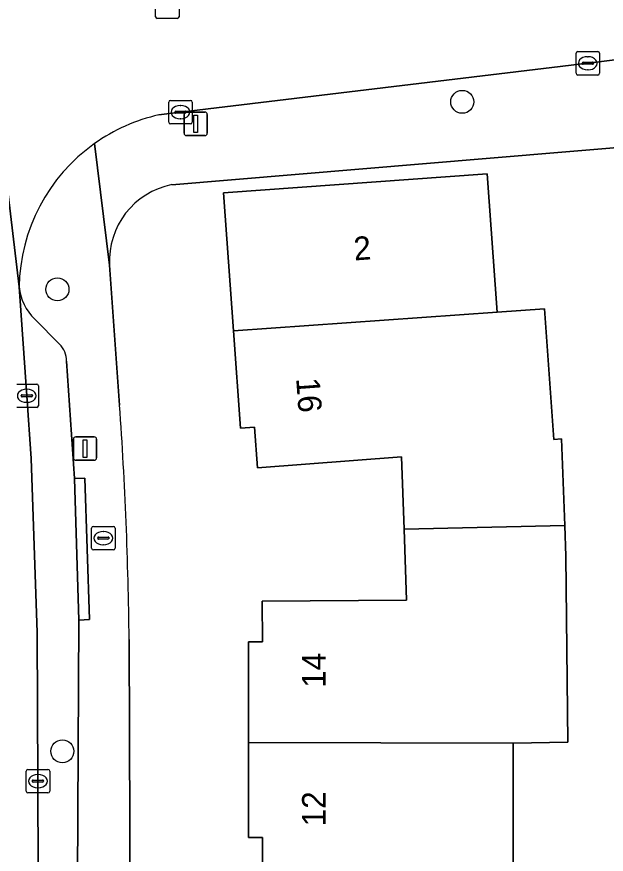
# Model space of a CAD drawing. Extents: x 162879 to 165540, y 384011 to 385181.
# Drawn here: x 163797.54 to 163822.64, y 384339.68 to 384375.35 of the extents above; entities that cross this region are included whole.
import ezdxf

# ---------------------------------------------------------------- set-up
doc = ezdxf.new("R2010")
doc.units = 0
for name, color, linetype in [('IMGEO_Boom', 7, 'Continuous'), ('IMGEO_Brandkraan', 7, 'Continuous'), ('IMGEO_Erf', 7, 'Continuous'), ('IMGEO_Kolk', 7, 'Continuous'), ('IMGEO_Lichtmast', 7, 'Continuous'), ('IMGEO_Muur', 7, 'Continuous'), ('IMGEO_Pand', 7, 'Continuous'), ('IMGEO_Pand_nummerreeks', 7, 'Continuous'), ('IMGEO_Parkeervlak_open', 7, 'Continuous'), ('IMGEO_Rijbaan_lokaal_open', 7, 'Continuous'), ('IMGEO_Voetpad_open', 7, 'Continuous')]:
    doc.layers.add(name, color=color, linetype=linetype)

msp = doc.modelspace()

# ---------------------------------------------------------------- linework, layer by layer
at = {"layer": 'IMGEO_Boom'}
for centre in [(163816.507, 384371.726), (163799.272, 384363.738), (163799.484, 384344.065)]:
    msp.add_circle(centre, 0.489, dxfattribs=at)
at = {"layer": 'IMGEO_Brandkraan'}
for p, q in [((163800.727, 384352.718), (163800.727, 384353.57)), ((163800.802, 384353.644), (163801.654, 384353.644)), ((163801.728, 384353.57), (163801.728, 384352.718)), ((163801.215, 384353.424), (163801.24, 384353.424)), ((163800.986, 384353.138), (163800.986, 384353.15)), ((163801.424, 384353.101), (163801.026, 384353.101)), ((163801.029, 384353.187), (163801.427, 384353.187)), ((163801.238, 384352.864), (163801.213, 384352.864)), ((163801.47, 384353.15), (163801.47, 384353.138)), ((163801.654, 384352.644), (163800.802, 384352.644))]:
    msp.add_line(p, q, dxfattribs=at)
for points in [[(163800.727, 384352.718), (163800.727, 384353.57)], [(163800.802, 384353.644), (163801.654, 384353.644)], [(163801.728, 384353.57), (163801.728, 384352.718)], [(163801.654, 384352.644), (163800.802, 384352.644)]]:
    msp.add_lwpolyline(points, dxfattribs=at)
for centre, radius, start, end in [((163800.804, 384353.568), 0.0765, 91.552, 178.448), ((163800.804, 384353.568), 0.0765, 91.552, 178.448), ((163801.652, 384353.568), 0.0765, 1.552, 88.448), ((163801.652, 384353.568), 0.0765, 1.552, 88.448), ((163801.026, 384353.147), 0.0403, 85.8775, 175.7526), ((163801.023, 384353.137), 0.0366, 178.938, 274.7102), ((163801.427, 384353.144), 0.043, 264.8664, 352.4533), ((163801.431, 384353.149), 0.0386, 1.7309, 96.639), ((163800.804, 384352.72), 0.0765, 181.552, 268.448), ((163800.804, 384352.72), 0.0765, 181.552, 268.448), ((163801.652, 384352.72), 0.0765, 271.552, 358.448), ((163801.652, 384352.72), 0.0765, 271.552, 358.448)]:
    msp.add_arc(centre, radius, start, end, dxfattribs=at)
for centre, major_axis, ratio, start_param, end_param in [((163801.214, 384353.144), (-0.387, 0.002), 0.722429, 4.712389, 7.853982), ((163801.239, 384353.144), (-0.39, 0.002), 0.717154, 1.570796, 4.712389)]:
    msp.add_ellipse(centre, major_axis=major_axis, ratio=ratio, start_param=start_param, end_param=end_param, dxfattribs=at)
at = {"layer": 'IMGEO_Erf'}
for points in [[(163871.845, 384381.733), (163828.311, 384370.22), (163828.207, 384370.211), (163817.519, 384369.317), (163804.137, 384368.197)], [(163808.008, 384338.663), (163808.008, 384340.393), (163807.408, 384340.393), (163807.408, 384344.433), (163807.408, 384348.733), (163808.008, 384348.733), (163807.996, 384350.455), (163814.136, 384350.498), (163814.032, 384353.524), (163813.926, 384356.611), (163807.795, 384356.132), (163807.659, 384357.872), (163807.061, 384357.829), (163806.762, 384361.971), (163806.338, 384367.853), (163817.574, 384368.663), (163817.999, 384362.768), (163820.004, 384362.913), (163820.406, 384357.348), (163820.735, 384357.372), (163820.87, 384353.677), (163820.918, 384352.376), (163821.006, 384344.449), (163818.676, 384344.414), (163818.677, 384339.004)], [(163801.492, 384364.772), (163801.92, 384358.803)], [(163802.324, 384348.829), (163802.427, 384320.83)]]:
    msp.add_lwpolyline(points, dxfattribs=at)
for centre, radius, start, end in [((163804.796, 384364.955), 3.309, 101.4804, 183.1645), ((163636.355, 384347.102), 165.978, 0.59633, 4.0427)]:
    msp.add_arc(centre, radius, start, end, dxfattribs=at)
at = {"layer": 'IMGEO_Kolk'}
for p, q in [((163803.448, 384375.349), (163803.448, 384376.201)), ((163804.449, 384376.201), (163804.449, 384375.349)), ((163804.375, 384375.275), (163803.523, 384375.275)), ((163821.351, 384372.94), (163821.351, 384373.792)), ((163821.426, 384373.866), (163822.278, 384373.866)), ((163821.839, 384373.646), (163821.864, 384373.646)), ((163822.352, 384373.792), (163822.352, 384372.94)), ((163821.61, 384373.36), (163821.61, 384373.372)), ((163822.048, 384373.323), (163821.65, 384373.323)), ((163821.653, 384373.409), (163822.051, 384373.409)), ((163822.094, 384373.372), (163822.094, 384373.36)), ((163822.278, 384372.866), (163821.426, 384372.866)), ((163821.862, 384373.086), (163821.837, 384373.086)), ((163804.085, 384371.784), (163804.937, 384371.784)), ((163804.01, 384370.858), (163804.01, 384371.71)), ((163804.498, 384371.564), (163804.523, 384371.564)), ((163805.011, 384371.71), (163805.011, 384370.858)), ((163804.269, 384371.278), (163804.269, 384371.29)), ((163804.707, 384371.241), (163804.309, 384371.241)), ((163804.312, 384371.327), (163804.71, 384371.327)), ((163804.753, 384371.29), (163804.753, 384371.278)), ((163804.937, 384370.784), (163804.085, 384370.784)), ((163804.521, 384371.004), (163804.496, 384371.004)), ((163797.541, 384359.707), (163798.393, 384359.707)), ((163798.467, 384359.633), (163798.467, 384358.781)), ((163797.954, 384359.487), (163797.979, 384359.487)), ((163797.725, 384359.201), (163797.725, 384359.213)), ((163798.163, 384359.164), (163797.765, 384359.164)), ((163797.768, 384359.25), (163798.166, 384359.25)), ((163797.977, 384358.927), (163797.952, 384358.927)), ((163798.209, 384359.213), (163798.209, 384359.201)), ((163798.393, 384358.707), (163797.541, 384358.707)), ((163797.942, 384342.369), (163797.942, 384343.221)), ((163798.017, 384343.295), (163798.869, 384343.295)), ((163798.943, 384343.221), (163798.943, 384342.369)), ((163798.43, 384343.075), (163798.455, 384343.075)), ((163798.201, 384342.789), (163798.201, 384342.801)), ((163798.639, 384342.752), (163798.241, 384342.752)), ((163798.244, 384342.838), (163798.642, 384342.838)), ((163798.453, 384342.515), (163798.428, 384342.515)), ((163798.685, 384342.801), (163798.685, 384342.789)), ((163798.869, 384342.295), (163798.017, 384342.295))]:
    msp.add_line(p, q, dxfattribs=at)
for points in [[(163803.448, 384375.349), (163803.448, 384376.201)], [(163804.449, 384376.201), (163804.449, 384375.349)], [(163804.375, 384375.275), (163803.523, 384375.275)], [(163821.351, 384372.94), (163821.351, 384373.792)], [(163821.426, 384373.866), (163822.278, 384373.866)], [(163822.352, 384373.792), (163822.352, 384372.94)], [(163822.278, 384372.866), (163821.426, 384372.866)], [(163804.085, 384371.784), (163804.937, 384371.784)], [(163804.01, 384370.858), (163804.01, 384371.71)], [(163805.011, 384371.71), (163805.011, 384370.858)], [(163804.937, 384370.784), (163804.085, 384370.784)], [(163797.541, 384359.707), (163798.393, 384359.707)], [(163798.467, 384359.633), (163798.467, 384358.781)], [(163798.393, 384358.707), (163797.541, 384358.707)], [(163797.942, 384342.369), (163797.942, 384343.221)], [(163798.017, 384343.295), (163798.869, 384343.295)], [(163798.943, 384343.221), (163798.943, 384342.369)], [(163798.869, 384342.295), (163798.017, 384342.295)]]:
    msp.add_lwpolyline(points, dxfattribs=at)
for centre, radius, start, end in [((163803.525, 384375.351), 0.0765, 181.552, 268.448), ((163803.525, 384375.351), 0.0765, 181.552, 268.448), ((163804.373, 384375.351), 0.0765, 271.552, 358.448), ((163804.373, 384375.351), 0.0765, 271.552, 358.448), ((163821.428, 384373.79), 0.0765, 91.552, 178.448), ((163821.428, 384373.79), 0.0765, 91.552, 178.448), ((163822.276, 384373.79), 0.0765, 1.552, 88.448), ((163822.276, 384373.79), 0.0765, 1.552, 88.448), ((163821.65, 384373.369), 0.0403, 85.8775, 175.7526), ((163821.647, 384373.359), 0.0366, 178.938, 274.7102), ((163822.051, 384373.366), 0.043, 264.8664, 352.4533), ((163822.055, 384373.371), 0.0386, 1.7309, 96.639), ((163821.428, 384372.942), 0.0765, 181.552, 268.448), ((163821.428, 384372.942), 0.0765, 181.552, 268.448), ((163822.276, 384372.942), 0.0765, 271.552, 358.448), ((163822.276, 384372.942), 0.0765, 271.552, 358.448), ((163804.087, 384371.708), 0.0765, 91.552, 178.448), ((163804.087, 384371.708), 0.0765, 91.552, 178.448), ((163804.935, 384371.708), 0.0765, 1.552, 88.448), ((163804.935, 384371.708), 0.0765, 1.552, 88.448), ((163804.309, 384371.287), 0.0403, 85.8775, 175.7526), ((163804.306, 384371.277), 0.0366, 178.938, 274.7102), ((163804.71, 384371.284), 0.043, 264.8664, 352.4533), ((163804.714, 384371.289), 0.0386, 1.7309, 96.639), ((163804.087, 384370.86), 0.0765, 181.552, 268.448), ((163804.087, 384370.86), 0.0765, 181.552, 268.448), ((163804.935, 384370.86), 0.0765, 271.552, 358.448), ((163804.935, 384370.86), 0.0765, 271.552, 358.448), ((163798.391, 384359.631), 0.0765, 1.552, 88.448), ((163798.391, 384359.631), 0.0765, 1.552, 88.448), ((163797.765, 384359.21), 0.0403, 85.8775, 175.7526), ((163797.762, 384359.2), 0.0366, 178.938, 274.7102), ((163798.166, 384359.207), 0.043, 264.8664, 352.4533), ((163798.17, 384359.212), 0.0386, 1.7309, 96.639), ((163798.391, 384358.783), 0.0765, 271.552, 358.448), ((163798.391, 384358.783), 0.0765, 271.552, 358.448), ((163798.019, 384343.219), 0.0765, 91.552, 178.448), ((163798.019, 384343.219), 0.0765, 91.552, 178.448), ((163798.867, 384343.219), 0.0765, 1.552, 88.448), ((163798.867, 384343.219), 0.0765, 1.552, 88.448), ((163798.241, 384342.798), 0.0403, 85.8775, 175.7526), ((163798.238, 384342.788), 0.0366, 178.938, 274.7102), ((163798.642, 384342.795), 0.043, 264.8664, 352.4533), ((163798.646, 384342.8), 0.0386, 1.7309, 96.639), ((163798.019, 384342.371), 0.0765, 181.552, 268.448), ((163798.019, 384342.371), 0.0765, 181.552, 268.448), ((163798.867, 384342.371), 0.0765, 271.552, 358.448), ((163798.867, 384342.371), 0.0765, 271.552, 358.448)]:
    msp.add_arc(centre, radius, start, end, dxfattribs=at)
for centre, major_axis, ratio, start_param, end_param in [((163821.838, 384373.366), (-0.387, 0.002), 0.722429, 4.712389, 7.853982), ((163821.863, 384373.366), (-0.39, 0.002), 0.717154, 1.570796, 4.712389), ((163804.497, 384371.284), (-0.387, 0.002), 0.722429, 4.712389, 7.853982), ((163804.522, 384371.284), (-0.39, 0.002), 0.717154, 1.570796, 4.712389), ((163797.953, 384359.207), (-0.387, 0.002), 0.722429, 4.712389, 7.853982), ((163797.978, 384359.207), (-0.39, 0.002), 0.717154, 1.570796, 4.712389), ((163798.429, 384342.795), (-0.387, 0.002), 0.722429, 4.712389, 7.853982), ((163798.454, 384342.795), (-0.39, 0.002), 0.717154, 1.570796, 4.712389)]:
    msp.add_ellipse(centre, major_axis=major_axis, ratio=ratio, start_param=start_param, end_param=end_param, dxfattribs=at)
at = {"layer": 'IMGEO_Lichtmast'}
for p, q in [((163804.664, 384370.388), (163804.664, 384371.188)), ((163804.664, 384371.188), (163804.664, 384370.388)), ((163804.764, 384371.288), (163805.554, 384371.288)), ((163805.554, 384371.288), (163804.764, 384371.288)), ((163805.654, 384371.188), (163805.654, 384370.388)), ((163805.654, 384370.388), (163805.654, 384371.188)), ((163805.554, 384370.288), (163804.764, 384370.288)), ((163804.764, 384370.288), (163805.554, 384370.288)), ((163799.952, 384356.558), (163799.952, 384357.358)), ((163799.952, 384357.358), (163799.952, 384356.558)), ((163800.052, 384357.458), (163800.842, 384357.458)), ((163800.842, 384357.458), (163800.052, 384357.458)), ((163800.942, 384357.358), (163800.942, 384356.558)), ((163800.942, 384356.558), (163800.942, 384357.358)), ((163800.842, 384356.458), (163800.052, 384356.458)), ((163800.052, 384356.458), (163800.842, 384356.458))]:
    msp.add_line(p, q, dxfattribs=at)
for points in [[(163805.084, 384371.163), (163805.234, 384371.163), (163805.234, 384370.413), (163805.084, 384370.413), (163805.084, 384371.163)], [(163800.372, 384357.333), (163800.522, 384357.333), (163800.522, 384356.583), (163800.372, 384356.583), (163800.372, 384357.333)]]:
    msp.add_lwpolyline(points, dxfattribs=at)
for centre, start, end in [((163804.764, 384371.188), 90, 180), ((163804.764, 384371.188), 90, 180), ((163805.554, 384371.188), 0, 90), ((163805.554, 384371.188), 360, 90), ((163804.764, 384370.388), 180, 270), ((163804.764, 384370.388), 180, 270), ((163805.554, 384370.388), 270, 0), ((163805.554, 384370.388), 270, 0), ((163800.052, 384357.358), 90, 180), ((163800.052, 384357.358), 90, 180), ((163800.842, 384357.358), 0, 90), ((163800.842, 384357.358), 360, 90), ((163800.052, 384356.558), 180, 270), ((163800.052, 384356.558), 180, 270), ((163800.842, 384356.558), 270, 0), ((163800.842, 384356.558), 270, 0)]:
    msp.add_arc(centre, 0.1, start, end, dxfattribs=at)
at = {"layer": 'IMGEO_Muur'}
msp.add_lwpolyline([(163817.519, 384369.317), (163828.207, 384370.211)], dxfattribs=at)
at = {"layer": 'IMGEO_Pand'}
for points in [[(163817.999, 384362.768), (163817.574, 384368.663), (163806.338, 384367.853), (163806.762, 384361.971)], [(163817.999, 384362.768), (163806.762, 384361.971), (163807.061, 384357.829), (163807.659, 384357.872), (163807.795, 384356.132), (163813.926, 384356.611), (163814.032, 384353.524), (163820.87, 384353.677), (163820.735, 384357.372), (163820.406, 384357.348), (163820.004, 384362.913)], [(163820.87, 384353.677), (163814.032, 384353.524), (163814.136, 384350.498), (163807.996, 384350.455), (163808.008, 384348.733), (163807.408, 384348.733), (163807.408, 384344.433), (163818.676, 384344.414), (163821.006, 384344.449), (163820.918, 384352.376)], [(163814.163, 384335.79), (163821.007, 384335.651), (163821.006, 384339.004), (163818.677, 384339.004), (163818.676, 384344.414), (163807.408, 384344.433), (163807.408, 384340.393), (163808.008, 384340.393), (163808.008, 384338.663), (163814.163, 384338.662)]]:
    msp.add_lwpolyline(points, close=True, dxfattribs=at)
at = {"layer": 'IMGEO_Parkeervlak_open'}
for points in [[(163797.641, 384363.843), (163797.966, 384359.207), (163798.161, 384356.538), (163798.415, 384349.126), (163798.442, 384342.795), (163798.514, 384323.297), (163798.524, 384322.164)], [(163799.355, 384361.402), (163798.312, 384362.467)], [(163800.186, 384349.654), (163799.994, 384355.68), (163799.66, 384360.68)], [(163800.042, 384324.606), (163800.088, 384332.633), (163800.123, 384338.651), (163800.186, 384349.654)]]:
    msp.add_lwpolyline(points, dxfattribs=at)
for centre, radius, start, end in [((163799.826, 384364.057), 2.196, 185.5935, 226.3984), ((163798.683, 384360.693), 0.977, 359.2642, 46.5379)]:
    msp.add_arc(centre, radius, start, end, dxfattribs=at)
at = {"layer": 'IMGEO_Rijbaan_lokaal_open'}
for points in [[(163793.942, 384348.009), (163793.966, 384342.761), (163794.029, 384323.01), (163794.044, 384316.879), (163794.053, 384313.108), (163794.058, 384311.269), (163798.545, 384311.271), (163798.527, 384321.799), (163798.524, 384322.125), (163798.524, 384322.164), (163798.514, 384323.297), (163798.442, 384342.795), (163798.415, 384349.126), (163798.161, 384356.538), (163797.966, 384359.207), (163797.641, 384363.843), (163795.608, 384380.841), (163795.273, 384382.782), (163794.151, 384389.233), (163792.968, 384394.876), (163792.001, 384398.994), (163790.769, 384403.93)], [(163795.608, 384380.841), (163797.641, 384363.843)], [(163803.596, 384371.169), (163804.511, 384371.285), (163821.852, 384373.367), (163824.051, 384373.635), (163824.303, 384373.665), (163827.488, 384374.039), (163828.118, 384374.191), (163835.992, 384376.295)]]:
    msp.add_lwpolyline(points, dxfattribs=at)
for centre, radius, start, end in [((163805.265, 384363.734), 7.62, 102.6542, 125.3908), ((163805.267, 384363.727), 7.627, 125.3714, 179.1278)]:
    msp.add_arc(centre, radius, start, end, dxfattribs=at)
at = {"layer": 'IMGEO_Voetpad_open'}
for points in [[(163804.137, 384368.197), (163817.519, 384369.317), (163828.207, 384370.211), (163828.311, 384370.22), (163871.845, 384381.733)], [(163824.303, 384373.665), (163824.051, 384373.635), (163821.852, 384373.367), (163804.511, 384371.285), (163803.596, 384371.169)], [(163800.852, 384369.946), (163801.492, 384364.772)], [(163801.492, 384364.772), (163800.852, 384369.946)], [(163801.92, 384358.803), (163801.492, 384364.772)], [(163798.312, 384362.467), (163799.355, 384361.402)], [(163799.66, 384360.68), (163799.994, 384355.68), (163800.439, 384355.703), (163800.638, 384349.682), (163800.186, 384349.654), (163800.123, 384338.651), (163800.712, 384338.654), (163800.724, 384332.635), (163800.088, 384332.633), (163800.042, 384324.606)], [(163802.343, 384316.246), (163802.427, 384320.83), (163802.324, 384348.829)]]:
    msp.add_lwpolyline(points, dxfattribs=at)
msp.add_lwpolyline([(163800.186, 384349.654), (163800.638, 384349.682), (163800.439, 384355.703), (163799.994, 384355.68)], close=True, dxfattribs=at)
for centre, radius, start, end in [((163805.265, 384363.734), 7.62, 102.6542, 125.3908), ((163805.267, 384363.727), 7.627, 125.3714, 179.1278), ((163804.796, 384364.955), 3.309, 101.4804, 183.1645), ((163799.826, 384364.057), 2.196, 185.5935, 226.3984), ((163798.683, 384360.693), 0.977, 359.2642, 46.5379), ((163636.355, 384347.102), 165.978, 0.59633, 4.0427)]:
    msp.add_arc(centre, radius, start, end, dxfattribs=at)

# ---------------------------------------------------------------- texts
at = {"layer": 'IMGEO_Pand_nummerreeks'}
for s, rotation, p in [('2', 4.1233, (163811.915, 384364.967)), ('16', 274.1254, (163809.435, 384359.943)), ('14', 90, (163810.688, 384346.769)), ('12', 90, (163810.688, 384340.872))]:
    msp.add_text(s, height=1, rotation=rotation, dxfattribs=at).set_placement(p)

doc.saveas('drawing.dxf')
